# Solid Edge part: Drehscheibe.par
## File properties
Author: helmut
Template: Normal.par
Last saved by: helmut
Revision: 2
Application: Solid Edge
Dichte: 7,79999702546 kg/dm^3
Genauigkeit: 0,010
Teilflächenrmatvorlage: Model Default
Coef. of Thermal Exp: 0.0
Thermal Conductivity: 0.0
Specific Heat: 0.0
Modulus of Elasticity: 0.0
Poission's Ratio: 0.0
Yield Stress: 0.0
Ultimate Stress: 0.0
Elongation: 0.0
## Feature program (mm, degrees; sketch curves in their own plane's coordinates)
sketch for "unnamed RevolvedProtrusion 1" plane through (0, 0, 0) normal (0, -1, 0) x-axis (1, 0, 0)
  line (0, 0) -> (60, 0)
  line (60, 0) -> (60, -15)
  line (60, -15) -> (20, -15)
  line (20, -15) -> (20, -32)
  line (20, -32) -> (5, -32)
  line (5, -32) -> (5, -40)
  line (5, -40) -> (0, -40)
  dimension (linear) = 5
  dimension (linear) = 5
revolve "unnamed RevolvedProtrusion 1" add finite 360 deg about sketch line (0, -40) -> (0, 0)
sketch for "unnamed Hole 1" plane through (0, 0, 0) normal (0, 0, 1) x-axis (0, 1, 0)
  hole centre (50, 0) bore radius 3
hole "unnamed Hole 1" through
sketch for "unnamed Hole 2" plane through (0, 0, 0) normal (0, 0, 1) x-axis (0, 1, 0)
  hole centre (-50, 0) bore radius 3
hole "unnamed Hole 2" through
pattern "unnamed Pattern 1" of "unnamed Hole 1", "unnamed Hole 2"
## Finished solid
Body 1: solid body, 9 faces, 10 edges, 0 vertices.
  Faces by surface: cylinder 5, plane 4
  Edges by curve: circle 10
Bounding box of the edges (mm): 120.000 x 120.000 x 40.000, from (-60, -60, -40) to (60, 60, 0).
Cylindrical faces by radius (mm): R3 x2, R5 x1, R20 x1, R60 x1
Planar faces by outward normal: +z 1, -z 3
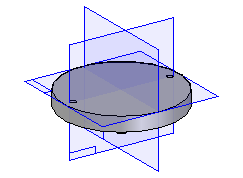
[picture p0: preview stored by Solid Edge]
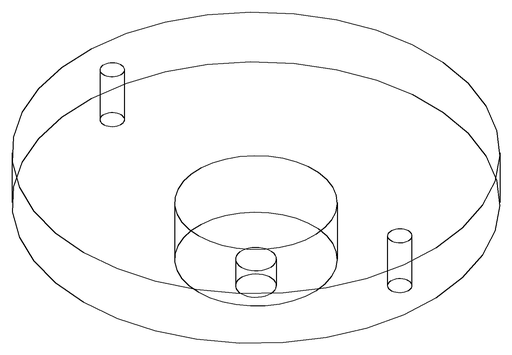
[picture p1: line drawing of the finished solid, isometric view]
